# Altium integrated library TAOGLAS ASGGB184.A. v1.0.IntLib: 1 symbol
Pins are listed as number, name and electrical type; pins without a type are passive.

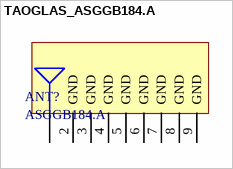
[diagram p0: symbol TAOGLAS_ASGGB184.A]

## TAOGLAS_ASGGB184.A
designator ANT?, comment ASGGB184.A
GPS/GLONASS/BeiDou/Galileo SMD Active Patch / with Embedded Active Circuitry; ComponentLibStatus: Created; MFG: Taoglas; Temp_High: +85C; Temp_Low: -40C
footprint ASGGB184.A (GPS/GLONASS/BeiDou/Galileo SMD Active Patch  with Embedded Active Circuitry)
pins: 1 RF, 2 GND, 3 GND, 4 GND, 5 GND, 6 GND, 7 GND, 8 GND, 9 GND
